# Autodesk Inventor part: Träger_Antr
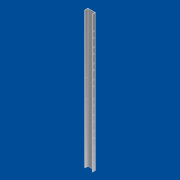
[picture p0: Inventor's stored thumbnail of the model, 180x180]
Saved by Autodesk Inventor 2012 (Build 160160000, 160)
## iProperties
Company: CAD-Verlag
Shininess: 64.0
Length Units: 11269
Angle Units: 11279
Time Units: 11290
Mass Units: 11283
Length Display Precision: 3
Angle Display Precision: 2
Compacted: True
Part Number: Träger_Antr
Document SubType Name: Modeling
Created: 2004-09
Material: Standard
Designer: Greiling
Manufacturer: Standard
Standards Organization: Custom
Density: 1 g/cm^3
Density: 0.0
Volumn: 0.0
Area: 0.0
PropertySet Name: Model Information
Control State: 0
Master: False
Checked Out: False
Author: Jürgen Kronas
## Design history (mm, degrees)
sketch "Skizze1"
  geometry: L1 (0, 1365.658)-(0, -105.051) reference; L2 (-133.06, 0)-(1729.776, 0) reference; L3 (-133.06, 0)-(1729.776, 0) reference; L4 (0, -105.051)-(0, 1365.658) reference; L5 (0, 0)-(0, 160); L6 (65, 0)-(0, 0); L7 (65, 2.822)-(65, 0); L8 (17.163, 11.727)-(59.939, 8.305); L9 (7.5, 137.806)-(7.5, 22.194); L10 (65, 160)-(65, 157.178); L11 (59.939, 151.695)-(17.163, 148.273); L12 (0, 160)-(65, 160); A1 r 10.5 centre (18, 137.806) between (17.163, 148.273) and (7.5, 137.806); A2 r 10.5 centre (18, 22.194) between (7.5, 22.194) and (17.163, 11.727); A3 r 5.5 centre (59.5, 2.822) between (65, 2.822) and (59.939, 8.305); A4 r 5.5 centre (59.5, 157.178) between (59.939, 151.695) and (65, 157.178); 1 further point
  constraints: 16 end point, 8 point on circle, 4 centre point, 3 point on line
extrude "Extrusion1" new body sketch "Skizze1" distance "d0" = 2800; taper "d1" = 0 deg
sketch "Skizze2" dims "d33" = 10, "d40" = 10, "d47" = 10, "d54" = 10, "d61" = 10
  geometry: L1 (-2378.43, 31.984)-(-2361.959, 32.005); L2 (-2378.227, 18.005)-(-2361.95, 18.005); L3 (-2495.554, 31.999)-(-2479.45, 32); L4 (-2495.45, 18)-(-2479.45, 18); L5 (-2800, 65)-(-2800, 0) reference; L6 (0, 65)-(-2800, 65) reference; L7 (-2092.477, 18.005)-(-2076.2, 18.005); L8 (-2092.68, 31.984)-(-2076.209, 32.005); L9 (-2209.7, 18)-(-2193.7, 18); L10 (-2209.804, 31.999)-(-2193.7, 32); L11 (-1924.054, 31.999)-(-1907.95, 32); L12 (-1923.95, 18)-(-1907.95, 18); L13 (-1806.93, 31.984)-(-1790.459, 32.005); L14 (-1806.727, 18.005)-(-1790.45, 18.005); L15 (-1638.304, 31.999)-(-1622.2, 32); L16 (-1638.2, 18)-(-1622.2, 18); L17 (-1520.977, 18.005)-(-1504.7, 18.005); L18 (-1521.18, 31.984)-(-1504.709, 32.005); L19 (-1295.404, 31.999)-(-1279.3, 32); L20 (-1295.3, 18)-(-1279.3, 18); L21 (-1178.28, 31.984)-(-1161.809, 32.005); L22 (-1178.077, 18.005)-(-1161.8, 18.005); L23 (-892.53, 31.984)-(-876.059, 32.005); L24 (-892.327, 18.005)-(-876.05, 18.005); L25 (-1009.654, 31.999)-(-993.55, 32); L26 (-1009.55, 18)-(-993.55, 18); L27 (-606.78, 31.984)-(-590.309, 32.005); L28 (-606.577, 18.005)-(-590.3, 18.005); L29 (-723.904, 31.999)-(-707.8, 32); L30 (-723.8, 18)-(-707.8, 18); L31 (-321.03, 31.984)-(-304.559, 32.005); L32 (-320.827, 18.005)-(-304.55, 18.005); L33 (-438.154, 31.999)-(-422.05, 32); L34 (-438.05, 18)-(-422.05, 18); A1 r 7 centre (-2377.95, 25) between (-2377.489, 31.985) and (-2378.227, 18.005); A2 r 7 centre (-2361.95, 25.005) between (-2361.95, 18.005) and (-2361.959, 32.005); A3 r 7 centre (-2495.45, 25) between (-2495.347, 31.999) and (-2495.45, 18); A4 r 7 centre (-2479.45, 25) between (-2479.45, 18) and (-2479.45, 32); A5 r 7 centre (-2076.2, 25.005) between (-2076.2, 18.005) and (-2076.209, 32.005); A6 r 7 centre (-2092.2, 25) between (-2091.739, 31.985) and (-2092.477, 18.005); A7 r 7 centre (-2193.7, 25) between (-2193.7, 18) and (-2193.7, 32); A8 r 7 centre (-2209.7, 25) between (-2209.597, 31.999) and (-2209.7, 18); A9 r 7 centre (-1923.95, 25) between (-1923.847, 31.999) and (-1923.95, 18); A10 r 7 centre (-1907.95, 25) between (-1907.95, 18) and (-1907.95, 32); A11 r 7 centre (-1806.45, 25) between (-1805.989, 31.985) and (-1806.727, 18.005); A12 r 7 centre (-1790.45, 25.005) between (-1790.45, 18.005) and (-1790.459, 32.005); A13 r 7 centre (-1622.2, 25) between (-1622.2, 18) and (-1622.2, 32); A14 r 7 centre (-1504.7, 25.005) between (-1504.7, 18.005) and (-1504.709, 32.005); A15 r 7 centre (-1520.7, 25) between (-1520.239, 31.985) and (-1520.977, 18.005); A16 r 7 centre (-1638.2, 25) between (-1638.097, 31.999) and (-1638.2, 18); A17 r 7 centre (-1295.3, 25) between (-1295.197, 31.999) and (-1295.3, 18); A18 r 7 centre (-1279.3, 25) between (-1279.3, 18) and (-1279.3, 32); A19 r 7 centre (-1177.8, 25) between (-1177.339, 31.985) and (-1178.077, 18.005); A20 r 7 centre (-1161.8, 25.005) between (-1161.8, 18.005) and (-1161.809, 32.005); A21 r 7 centre (-892.05, 25) between (-891.589, 31.985) and (-892.327, 18.005); A22 r 7 centre (-876.05, 25.005) between (-876.05, 18.005) and (-876.059, 32.005); A23 r 7 centre (-1009.55, 25) between (-1009.447, 31.999) and (-1009.55, 18); A24 r 7 centre (-993.55, 25) between (-993.55, 18) and (-993.55, 32); A25 r 7 centre (-606.3, 25) between (-605.839, 31.985) and (-606.577, 18.005); A26 r 7 centre (-590.3, 25.005) between (-590.3, 18.005) and (-590.309, 32.005); A27 r 7 centre (-723.8, 25) between (-723.697, 31.999) and (-723.8, 18); A28 r 7 centre (-707.8, 25) between (-707.8, 18) and (-707.8, 32); A29 r 7 centre (-320.55, 25) between (-320.089, 31.985) and (-320.827, 18.005); A30 r 7 centre (-304.55, 25.005) between (-304.55, 18.005) and (-304.559, 32.005); A31 r 7 centre (-438.05, 25) between (-437.947, 31.999) and (-438.05, 18); A32 r 7 centre (-422.05, 25) between (-422.05, 18) and (-422.05, 32); 32 further points
  constraints: 80 point on circle, 64 end point, 32 centre point, 32 coincident, 32 tangent, 16 point on line, 5 horizontal, 182 other
  dimensions: "d2" = 14 diameter of A1; "d3" = 14 diameter of A2; "d4" = 16 distance of A2.centre point (-2377.95, 25); "d7" = 14 diameter of A3; "d8" = 14 diameter of A4; "d9" = 16 distance of A4.centre point (-2495.45, 25); "d10" = 0 vertical distance of point (-2377.95, 25) point (-2479.45, 25); "d11" = 117.5 distance of point (-2495.45, 25) point (-2377.95, 25); "d12" = 304.55 distance from line of L5 point (-2495.45, 25); "d30" = 285.75 distance of L2.end L7.end; "d37" = 285.75 distance of A8.centre A9.centre; "d44" = 285.75 distance of L11.end L15.end; "d51" = 342.9 distance of L15.start L19.start; "d58" = 285.75 distance of A19.centre A21.centre; "d75" = 40 distance from line of L6 point (-2495.45, 25)
extrude "Extrusion2" cut sketch "Skizze2" stored distance "d5" = 2800; taper "d6" = 0 deg
sketch "Skizze3"
  geometry: L1 (115.613, 2800)-(0, 2800) reference; L2 (137.806, 0)-(137.806, 2800) reference; 4 further points
  dimensions: "d63" = 50 distance from line of point (87.806, 2500) L2; "d64" = 300 distance from line of point (87.806, 2500) L1; "d65" = 2500 distance from line of L1 point (87.806, 300); "d66" = 1750 distance from line of L1 point (87.806, 1050); "d67" = 1050 distance from line of L1 point (87.806, 1750)
hole "Bohrung1" sketch "Skizze3" at (87.806, 2500), (87.806, 1750), (87.806, 1050), (87.806, 300) diameter "d68" = 6.647; stored, may be unused: countersink angle "d72" = 82 deg, drill point angle "d74" = 118 deg; dims "d69" = 6, "d70" = 4, "d71" = 2, "d73" = 8
sketch "Skizze4"
  geometry: L1 (0, 65)-(2800, 65) reference; 2 further points
  dimensions: "d76" = 1210 horizontal distance of L1.start point (1210, 30); "d77" = 380 distance of point (1590, 30) point (1210, 30); "d78" = 35 distance from line of L1 point (1210, 30); "d79" = 35 distance from line of L1 point (1590, 30)
hole "Bohrung2" sketch "Skizze4" at (1210, 30), (1590, 30) diameter "d80" = 14; stored, may be unused: countersink angle "d84" = 82 deg, drill point angle "d86" = 118 deg; dims "d81" = 6, "d82" = 4, "d83" = 2, "d85" = 20
workplane "Arbeitsebene1"
node "Volumenkörper1"
node "Volumenkörpern"
node "Oberflächenkörpern"
